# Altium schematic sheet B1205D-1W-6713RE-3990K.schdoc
size 277 x 190 mm; Device: default297x210; Symbol: default297x210; Name: default297x210; Date: 2026.03.03; Rev: V1.0; Size: "A4"; Id: /; File: B1205D-1W-6713RE-3990K; Sheet: /
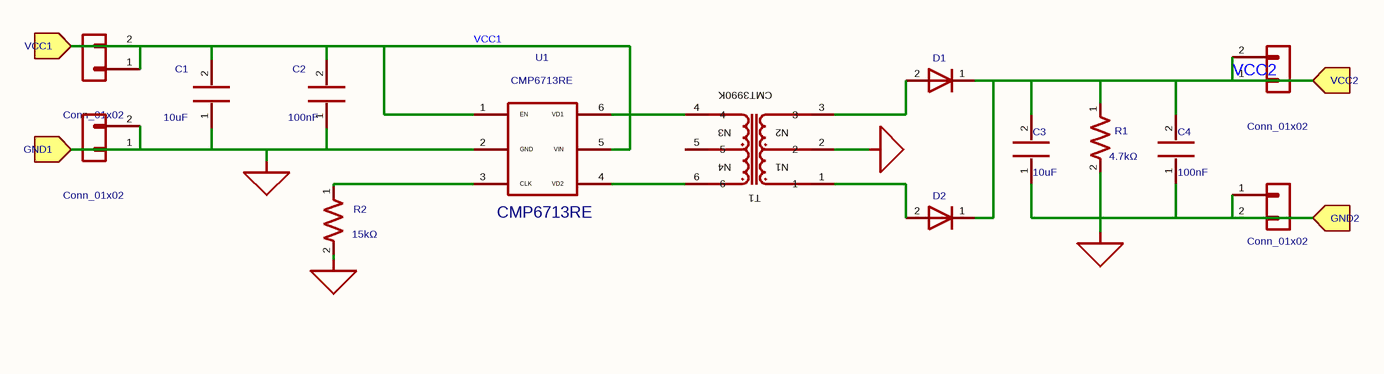
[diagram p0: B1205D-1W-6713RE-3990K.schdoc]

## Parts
C1  10uF  [MYLibrary:C0603]
C2  100nF  [MYLibrary:C0603]
C3  10uF  [MYLibrary:C0603]
C4  100nF  [MYLibrary:C0603]
D1  B5819WS  [MYLibrary:SOD-323]  (value not drawn)
D2  B5819WS  [MYLibrary:SOD-323]  (value not drawn)
J2  value Conn_01x02  [Connector_PinHeader_2.54mm:PinHeader_1x02_P2.54mm_Vertical]  (hidden comment: HX PZ2.54-1x2P ZZ)
J3  value Conn_01x02  [Connector_PinHeader_2.54mm:PinHeader_1x02_P2.54mm_Vertical]  (hidden comment: HX PZ2.54-1x2P ZZ)
J4  value Conn_01x02  [Connector_PinHeader_2.54mm:PinHeader_1x02_P2.54mm_Vertical]  (hidden comment: HX PZ2.54-1x2P ZZ)
J5  value Conn_01x02  [Connector_PinHeader_2.54mm:PinHeader_1x02_P2.54mm_Vertical]  (hidden comment: HX PZ2.54-1x2P ZZ)
R1  4.7kΩ  [MYLibrary:R0603]
R2  15kΩ  [MYLibrary:R0603]
T1  (no value)  [CMT3990K]
U1  CMP6713RE  [MYLibrary:SOT23-6]

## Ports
GND1 (in), GND2 (in), VCC1 (in), VCC2 (in)

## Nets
GND1: C1.1 C2.1 J3.1(Pin_1) J3.2(Pin_2) R2.2 U1.2(GND) ; port GND1
GND2: C3.1 C4.1 J5.1(Pin_1) J5.2(Pin_2) R1.2 T1.2 ; port GND2
VCC1: C1.2 C2.2 J2.1(Pin_1) J2.2(Pin_2) U1.1(EN) U1.5(VIN) ; port VCC1
VCC2: C3.2 C4.2 D1.1(K) D2.1(K) J4.1(Pin_1) J4.2(Pin_2) R1.1 ; port VCC2
NetD1_2: D1.2(A) T1.3
NetD2_2: D2.2(A) T1.1
NetR2_1: R2.1 U1.3(CLK)
NetT1_4: T1.4 U1.6(VD1)
NetT1_6: T1.6 U1.4(VD2)

Not connected (* = marked no-connect by the designer): T1 5

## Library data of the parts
C1 = 0603X106M250NT: 容值:10uF;精度:±20%;额定电压:25V;温度系数:X5R;; Manufacturer: FH(风华); Symbol: My_Library_C; Add into BOM: yes; 3D Model: 1ba041120af144c991958decab20d241; 3D Model Transform: 62.992,31.496,0,0,0,0,0,0,0; Tolerance: ±20%; Voltage Rating: 25V; Temperature Coefficient: X5R; ki_keywords: cap capacitor; ki_fp_filters: C_*; UniqueId: 5fb4f22ffcb6a001; ModelName: C0603_L1.6-W0.8-H0.8
C2 = CC0603KRX7R9BB104: 容值:100nF;精度:±10%;额定电压:50V;温度系数:X7R;; Manufacturer: YAGEO(国巨); Symbol: My_Library_C; Add into BOM: yes; 3D Model: ac125912035d415993ca9572d50418b1; 3D Model Transform: 62.992,31.496,0,0,0,0,0,0,0; Tolerance: ±10%; Voltage Rating: 50V; Temperature Coefficient: X7R; ki_keywords: cap capacitor; ki_fp_filters: C_*; UniqueId: 21d50210554cb61f; ModelName: C0603_L1.6-W0.8-H0.8
C3 = 0603X106M250NT: 容值:10uF;精度:±20%;额定电压:25V;温度系数:X5R;; Manufacturer: FH(风华); Symbol: My_Library_C; Add into BOM: yes; 3D Model: 1ba041120af144c991958decab20d241; 3D Model Transform: 62.992,31.496,0,0,0,0,0,0,0; Tolerance: ±20%; Voltage Rating: 25V; Temperature Coefficient: X5R; ki_keywords: cap capacitor; ki_fp_filters: C_*; UniqueId: ec64484c8c07847f; ModelName: C0603_L1.6-W0.8-H0.8
C4 = CC0603KRX7R9BB104: 容值:100nF;精度:±10%;额定电压:50V;温度系数:X7R;; Manufacturer: YAGEO(国巨); Symbol: My_Library_C; Add into BOM: yes; 3D Model: ac125912035d415993ca9572d50418b1; 3D Model Transform: 62.992,31.496,0,0,0,0,0,0,0; Tolerance: ±10%; Voltage Rating: 50V; Temperature Coefficient: X7R; ki_keywords: cap capacitor; ki_fp_filters: C_*; UniqueId: 623e2bb2442f04df; ModelName: C0603_L1.6-W0.8-H0.8
D1 = B5819WS_C64886: 二极管配置:独立式;正向压降(Vf):900mV@3A;直流反向耐压(Vr):40V;整流电流:1A;; Manufacturer: MDD(辰达半导体); Symbol: My_Library_D; Add into BOM: yes; 3D Model: 7459fe65e23146c0a8d836e46a0add72; 3D Model Transform: 104.3305,51.181,0,0,0,0,0,0,0; Diode Configuration: 独立式; Voltage - DC Reverse(Vr): 40V; Current - Rectified: 1A; Reverse Leakage Current (Ir): 1mA@40V; Operating Junction Temperature Range: -55℃~+125℃; Non-Repetitive Peak Forward Surge Current: 25A; Value: D; ki_keywords: diode; ki_fp_filters: TO-???* *_Diode_* *SingleDiode* D_*; UniqueId: 07a0d5848cd81316; ModelName: SOD-323_L1.8-W1.3-LS2.5-RD
D2 = B5819WS_C64886: 二极管配置:独立式;正向压降(Vf):900mV@3A;直流反向耐压(Vr):40V;整流电流:1A;; Manufacturer: MDD(辰达半导体); Symbol: My_Library_D; Add into BOM: yes; 3D Model: 7459fe65e23146c0a8d836e46a0add72; 3D Model Transform: 104.3305,51.181,0,0,0,0,0,0,0; Diode Configuration: 独立式; Voltage - DC Reverse(Vr): 40V; Current - Rectified: 1A; Reverse Leakage Current (Ir): 1mA@40V; Operating Junction Temperature Range: -55℃~+125℃; Non-Repetitive Peak Forward Surge Current: 25A; Value: D; ki_keywords: diode; ki_fp_filters: TO-???* *_Diode_* *SingleDiode* D_*; UniqueId: fa5cd661465da5bc; ModelName: SOD-323_L1.8-W1.3-LS2.5-RD
J2 = HX PZ2.54-1x2P ZZ: 插针结构:1x2P;间距:2.54mm;行距:-;圆针/方针:方针;安装方式:直插;排数:单排;总PIN位数:2P;额定电流:3A;额定电压:1kV;配合针长度:6mm;塑高:2.5mm;端接针长度:3mm;触头材质:黄铜;触头镀层:金;工作温度:-40℃~+105℃;颜色:黑色;; Manufacturer: hanxia(韩下); Symbol: Connector_Generic_Conn_01x02; Add into BOM: yes; 3D Model: c7a9f3c3e6e34627af2bf939e464cb35; 3D Model Transform: 200,100,0,0,0,0,0,0,-118.11; Pin Structure: 1x2P; Pitch: 2.54mm; Circluar Pins/Square Pins: 方针; Current Rating: 3A; Voltage Rating (Max): 1kV; ki_keywords: connector; ki_fp_filters: Connector*:*_1x??_*; UniqueId: 42913bc3a3449998; ModelName: HDR-TH_2P-P2.54-M-LI-1X2P
J3 = HX PZ2.54-1x2P ZZ: 插针结构:1x2P;间距:2.54mm;行距:-;圆针/方针:方针;安装方式:直插;排数:单排;总PIN位数:2P;额定电流:3A;额定电压:1kV;配合针长度:6mm;塑高:2.5mm;端接针长度:3mm;触头材质:黄铜;触头镀层:金;工作温度:-40℃~+105℃;颜色:黑色;; Manufacturer: hanxia(韩下); Symbol: Connector_Generic_Conn_01x02; Add into BOM: yes; 3D Model: c7a9f3c3e6e34627af2bf939e464cb35; 3D Model Transform: 200,100,0,0,0,0,0,0,-118.11; Pin Structure: 1x2P; Pitch: 2.54mm; Circluar Pins/Square Pins: 方针; Current Rating: 3A; Voltage Rating (Max): 1kV; ki_keywords: connector; ki_fp_filters: Connector*:*_1x??_*; UniqueId: 6ca7fcf0d18ad80e; ModelName: HDR-TH_2P-P2.54-M-LI-1X2P
J4 = HX PZ2.54-1x2P ZZ: 插针结构:1x2P;间距:2.54mm;行距:-;圆针/方针:方针;安装方式:直插;排数:单排;总PIN位数:2P;额定电流:3A;额定电压:1kV;配合针长度:6mm;塑高:2.5mm;端接针长度:3mm;触头材质:黄铜;触头镀层:金;工作温度:-40℃~+105℃;颜色:黑色;; Manufacturer: hanxia(韩下); Symbol: Connector_Generic_Conn_01x02; Add into BOM: yes; 3D Model: c7a9f3c3e6e34627af2bf939e464cb35; 3D Model Transform: 200,100,0,0,0,0,0,0,-118.11; Pin Structure: 1x2P; Pitch: 2.54mm; Circluar Pins/Square Pins: 方针; Current Rating: 3A; Voltage Rating (Max): 1kV; ki_keywords: connector; ki_fp_filters: Connector*:*_1x??_*; UniqueId: 048fde32f53a6793; ModelName: HDR-TH_2P-P2.54-M-LI-1X2P
J5 = HX PZ2.54-1x2P ZZ: 插针结构:1x2P;间距:2.54mm;行距:-;圆针/方针:方针;安装方式:直插;排数:单排;总PIN位数:2P;额定电流:3A;额定电压:1kV;配合针长度:6mm;塑高:2.5mm;端接针长度:3mm;触头材质:黄铜;触头镀层:金;工作温度:-40℃~+105℃;颜色:黑色;; Manufacturer: hanxia(韩下); Symbol: Connector_Generic_Conn_01x02; Add into BOM: yes; 3D Model: c7a9f3c3e6e34627af2bf939e464cb35; 3D Model Transform: 200,100,0,0,0,0,0,0,-118.11; Pin Structure: 1x2P; Pitch: 2.54mm; Circluar Pins/Square Pins: 方针; Current Rating: 3A; Voltage Rating (Max): 1kV; ki_keywords: connector; ki_fp_filters: Connector*:*_1x??_*; UniqueId: c38aec87e6867e62; ModelName: HDR-TH_2P-P2.54-M-LI-1X2P
R1 = RC0603FR-074K7L: 电阻类型:厚膜电阻;阻值:4.7kΩ;精度:±1%;功率:100mW;工作电压:75V;温度系数:±100ppm/℃;; Manufacturer: YAGEO(国巨); Symbol: My_Library_R; Add into BOM: yes; 3D Model: fc143cca1e79419f9cd78b61e9279f08; 3D Model Transform: 31.8897,63.7794,0,90,0,0,0,0,0; Tolerance: ±1%; Power(Watts): 100mW; Voltage-Supply(Max): 75V; ki_keywords: R res resistor; ki_fp_filters: R_*; UniqueId: 4e166b190d4de1c3; ModelName: R0603
R2 = RC0603FR-0715KL: 电阻类型:厚膜电阻;阻值:15kΩ;精度:±1%;功率:100mW;工作电压:75V;温度系数:±100ppm/℃;; Manufacturer: YAGEO(国巨); Symbol: My_Library_R; Add into BOM: yes; 3D Model: fc143cca1e79419f9cd78b61e9279f08; 3D Model Transform: 31.8897,63.7794,0,90,0,0,0,0,0; Tolerance: ±1%; Power(Watts): 100mW; Voltage-Supply(Max): 75V; ki_keywords: R res resistor; ki_fp_filters: R_*; UniqueId: 06442d24ab060343; ModelName: R0603
T1 = CMT3990K: AddInBom: yes
U1 = CMP6713RE: CMP6713RE 是全桥式变压器驱动器，芯片内部集成两个 N 型功率 MOSFET 和两个 P 型功率MOSFET，通过内部振荡器提供具有精准时序和死区时间的互补驱动信号。驱动器搭配配套的变压器，可以实现输入电压 6.5V-30V, 输出功率不超过2W 的隔离电源。采用不同的变压器，外围只需搭配简单的输入输出滤波电容，隔离变压器和整流电路，即可获得多种电压的非稳压输出。产品提供电阻选频功能，可以在 200-420 kHz 范围内连续调整开关频率，并且同时实现抖频。; Manufacturer: coileasy(线易); Symbol: MyLibrary_CMP6503; Add into BOM: yes; 3D Model: d6dbdad16bb04244b459daa2bbec6597; 3D Model Transform: 114.173,110.236,0,0,0,0,0,0,0; Input Voltage: 6.5V~30V; Current - Continuous Drain(Id): 300mA; Quiescent Current: 1.7mA; ModelName: SOT-23-6_L2.9-W1.6-P0.95-LS2.8-BL-2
